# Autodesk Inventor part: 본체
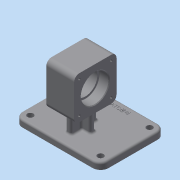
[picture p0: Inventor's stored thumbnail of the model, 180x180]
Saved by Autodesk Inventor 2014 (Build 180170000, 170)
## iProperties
Created: 2020-11
Part Number: 본체
Material: Generic
Document SubType Name: Modeling
Designer: kh
Density: 1 g/cm^3
Appearance: Default
Author: kh
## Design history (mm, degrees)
sketch "Sketch1"
  geometry: L1 (-65, -49)-(65, -49); L2 (65, -49)-(65, 49); L3 (65, 49)-(-65, 49); L4 (-65, 49)-(-65, -49); L5 (-65, -49)-(65, 49); L6 (65, -49)-(-65, 49); 1 further point
  constraints: 12 end point, 2 midpoint, 2 parallel, 1 horizontal, 1 perpendicular
  dimensions: "d0" = 130 distance of L2.end L3.end; "d1" = 98 distance of L1.end L2.end
extrude "Extrusion1" new body sketch "Sketch1" distance "d2" = 10; taper "d3" = 0 deg
workplane "Work Plane1"
sketch "Sketch2"
  geometry: L1 (44, -102)-(86, -102); L2 (86, -102)-(86, -38); L3 (86, -38)-(44, -38); L4 (44, -38)-(44, -102); L5 (130, 0)-(130, -10) reference; L6 (130, 0)-(0, 0) reference; 2 further points
  constraints: 8 end point, 2 parallel, 1 horizontal, 1 midpoint, 1 perpendicular, 1 vertical alignment
  dimensions: "d6" = 42 distance of L1.start L1.end; "d7" = 64 distance of L1.end L2.end; "d8" = 38 distance between parallel lines of L3 L6
extrude "Extrusion2" join sketch "Sketch2" stored distance "d9" = 64; taper "d10" = 0 deg
sketch "Sketch4"
  geometry: L1 (61, -38)-(61, -10); L2 (69, -38)-(69, -10); L3 (69, -10)-(61, -10); L4 (61, -38)-(69, -38); L5 (130, -10)-(0, -10) reference; L6 (86, -38)-(44, -38) reference; 2 further points
  constraints: 8 end point, 2 collinear, 2 parallel, 1 midpoint, 1 perpendicular, 1 vertical, 1 vertical alignment
  dimensions: "d11" = 8 distance of L1.start L2.start
extrude "Extrusion3" join sketch "Sketch4" stored distance "d12" = 40; taper "d13" = 0 deg
workplane "Work Plane3"
sketch "Sketch5"
  geometry: L1 (48, 38)-(48, 10); L2 (48, 10)-(82, 10); L3 (82, 10)-(82, 38); L4 (82, 38)-(48, 38); L5 (130, 10)-(0, 10) reference; L6 (86, 38)-(44, 38) reference; 2 further points
  constraints: 8 end point, 2 collinear, 2 parallel, 1 midpoint, 1 perpendicular, 1 vertical, 1 vertical alignment
  dimensions: "d14" = 34 distance of L1.end L2.end
extrude "Extrusion4" join sketch "Sketch5" stored distance "d15" = 8; taper "d16" = 0 deg
fillet "Fillet1" dims "d17" = 8
sketch "Sketch6"
  geometry: L1 (0, 48)-(0, 0) reference; L2 (-56, 56)-(-8, 56) reference; C1 r 21 at (-32, 24); 3 further points
  constraints: 2 midpoint, 1 centre point, 1 horizontal alignment, 1 vertical alignment
  dimensions: "d18" = 42 diameter of C1
extrude "Extrusion5" cut sketch "Sketch6" distance "d19" = 15; taper "d20" = 0 deg
sketch "Sketch7"
  geometry: C1 r 21 at (-32, 24) reference; 1 further point
hole "Hole1" sketch "Sketch7" at (-32, 24) diameter "d21" = 36; stored, may be unused: countersink angle "d25" = 90 deg, drill point angle "d27" = 118 deg; dims "d22" = 6, "d23" = 42, "d24" = 15, "d26" = 8
fillet "Fillet2" dims "d28" = 12
hole "Hole2" diameter "d31" = 9; stored, may be unused: countersink angle "d35" = 90 deg, drill point angle "d37" = 118 deg; dims "d29" = 10, "d30" = 10, "d32" = 6, "d33" = 42, "d34" = 15, "d36" = 8
pattern_linear "Rectangular Pattern1"
fillet "Fillet3" dims "d42" = 0.3
hole "Hole3" diameter "d45" = 3.242; stored, may be unused: countersink angle "d49" = 90 deg, drill point angle "d51" = 118 deg; dims "d43" = 10, "d44" = 10, "d46" = 8, "d47" = 42, "d48" = 15, "d50" = 10
pattern_linear "Rectangular Pattern2"
workplane "Work Plane4"
mirror "Mirror1"
chamfer "Chamfer1" distance "d56" = 1; stored, may be unused: second distance "d57" = 2, angle "d58" = 45 deg
sketch "Sketch9"
  geometry: L1 (65, -37)-(65, 37) reference; L2 (53, 49)-(-53, 49) reference; 2 further points
  constraints: 1 other
  dimensions: "d59" = 65 distance from line of L1 point (0, 39); "d60" = 10 distance from line of L2 point (0, 39)
emboss "Emboss1" sketch "Sketch9" dims "d0" = 130, "d1" = 98, "d11" = 8, "d61" = 0.5, "d62" = 0
fillet "Fillet4" dims "d63" = 3
fillet "Fillet5" dims "d64" = 3
body "Solid1"
other parameters: "d4" = -62
